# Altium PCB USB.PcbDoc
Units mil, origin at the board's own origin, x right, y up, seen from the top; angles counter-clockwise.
Board outline 5000 x 4000 mil, 2 copper layers (Top Layer, Bottom Layer); 19 components, 24 nets, 79 pads, 4 vias.
Unrouted connection lines stored in the file: 1.
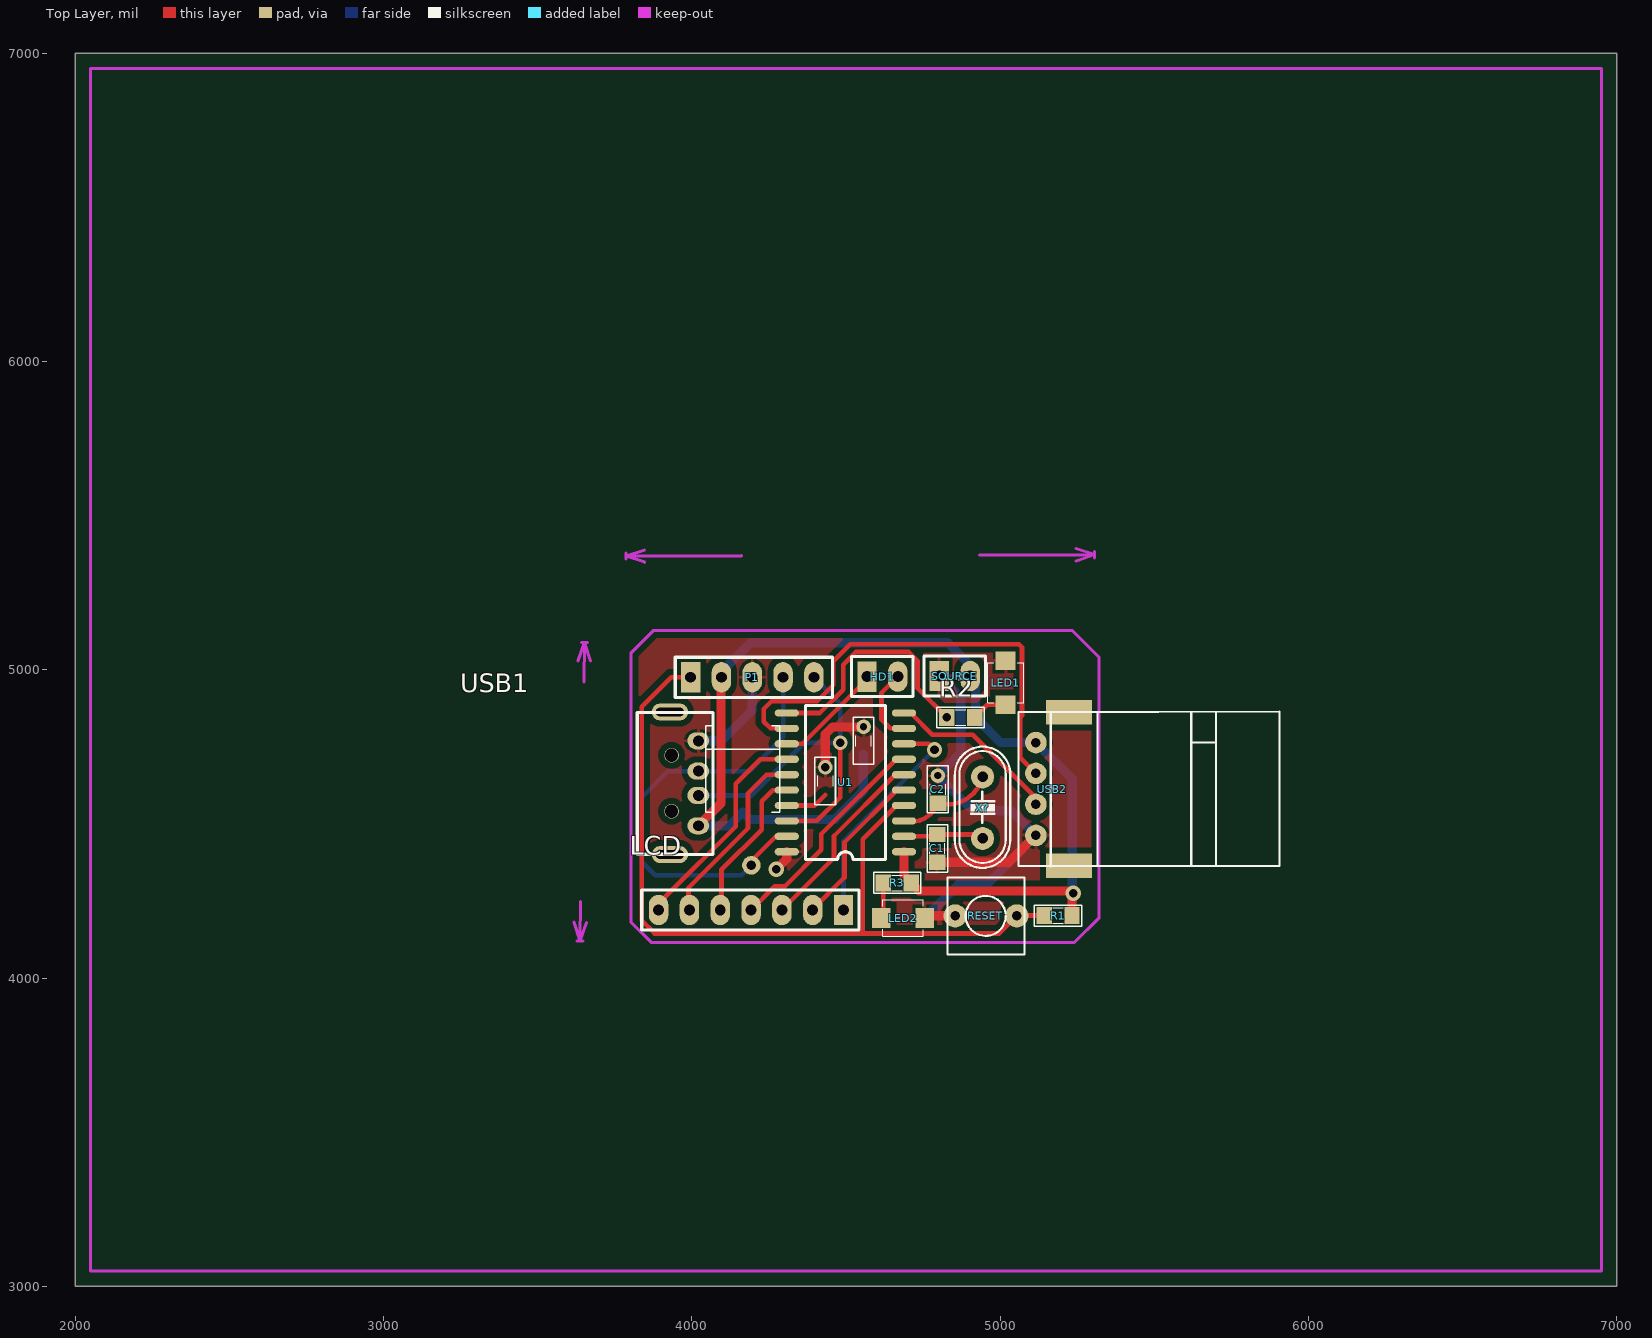
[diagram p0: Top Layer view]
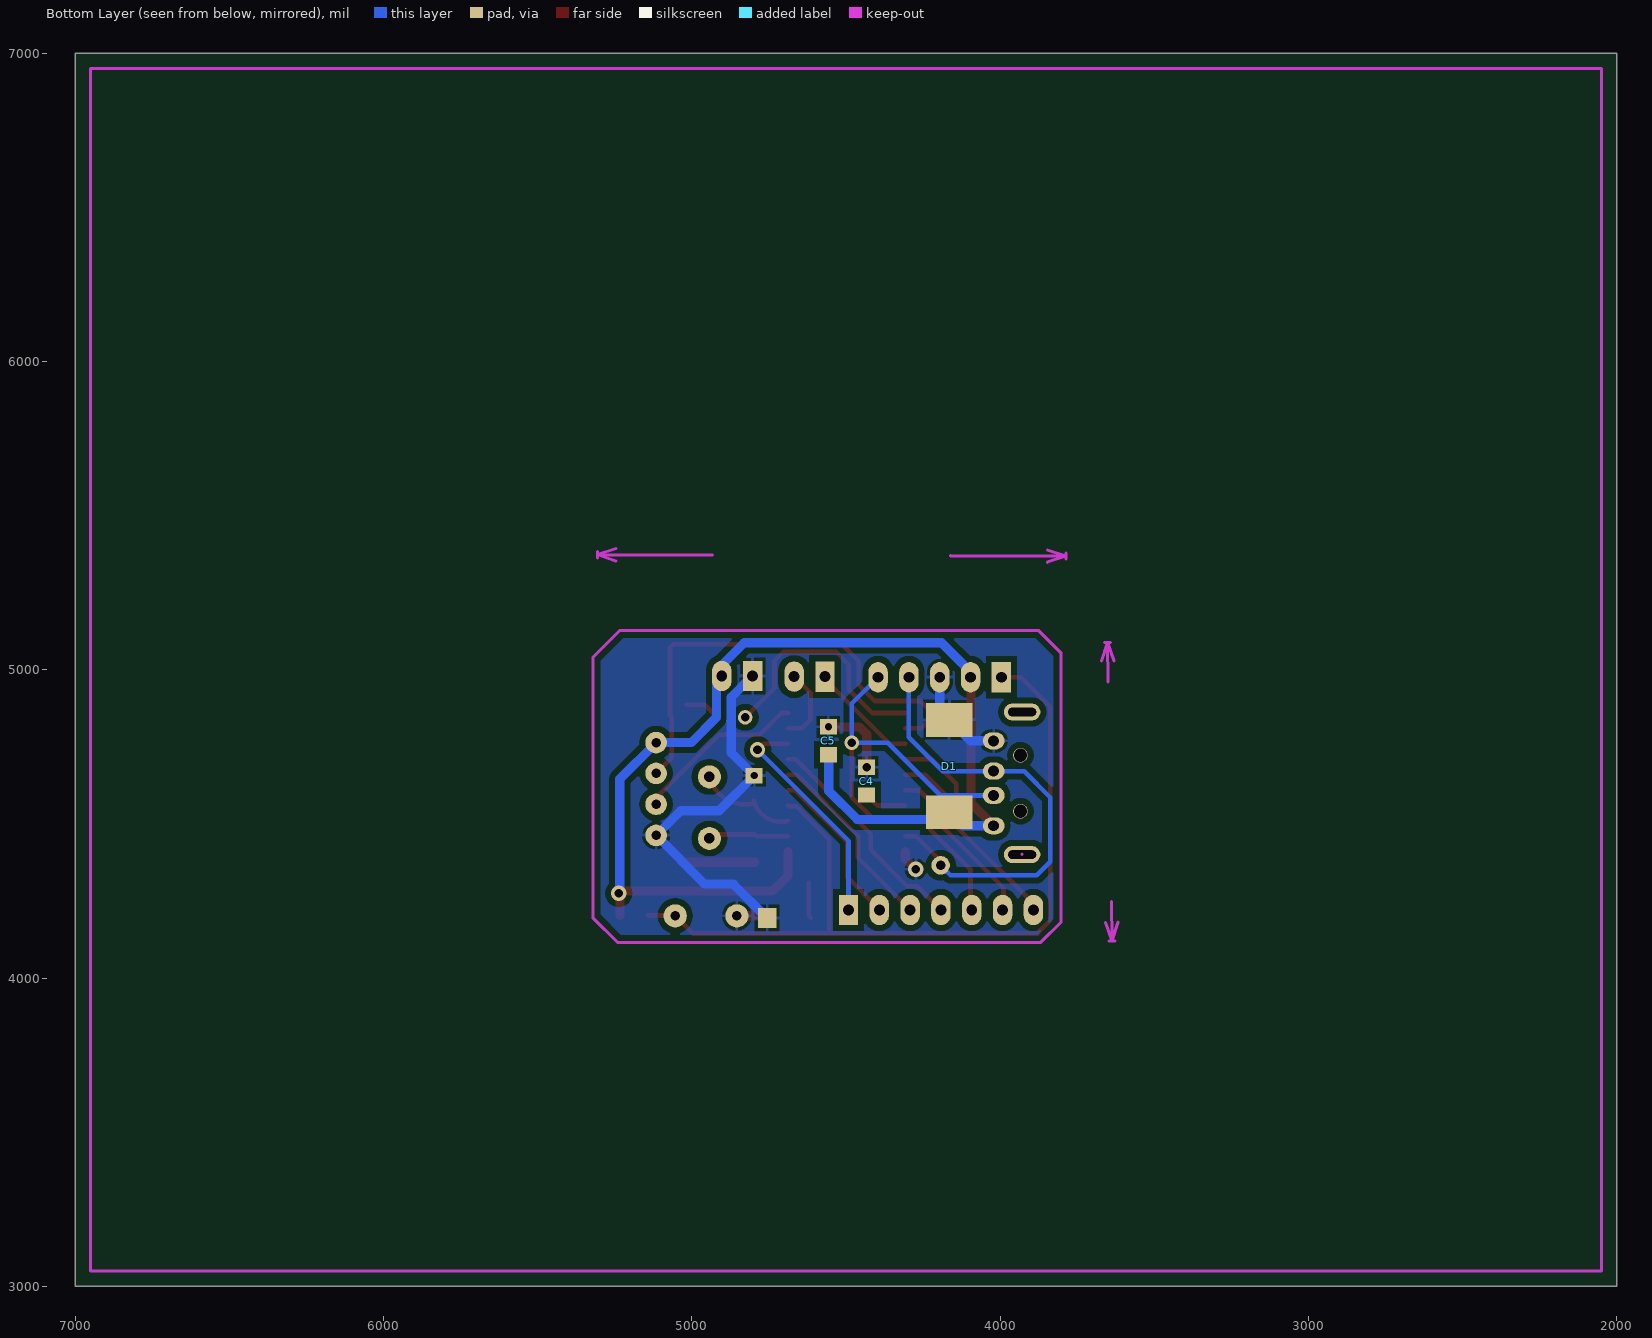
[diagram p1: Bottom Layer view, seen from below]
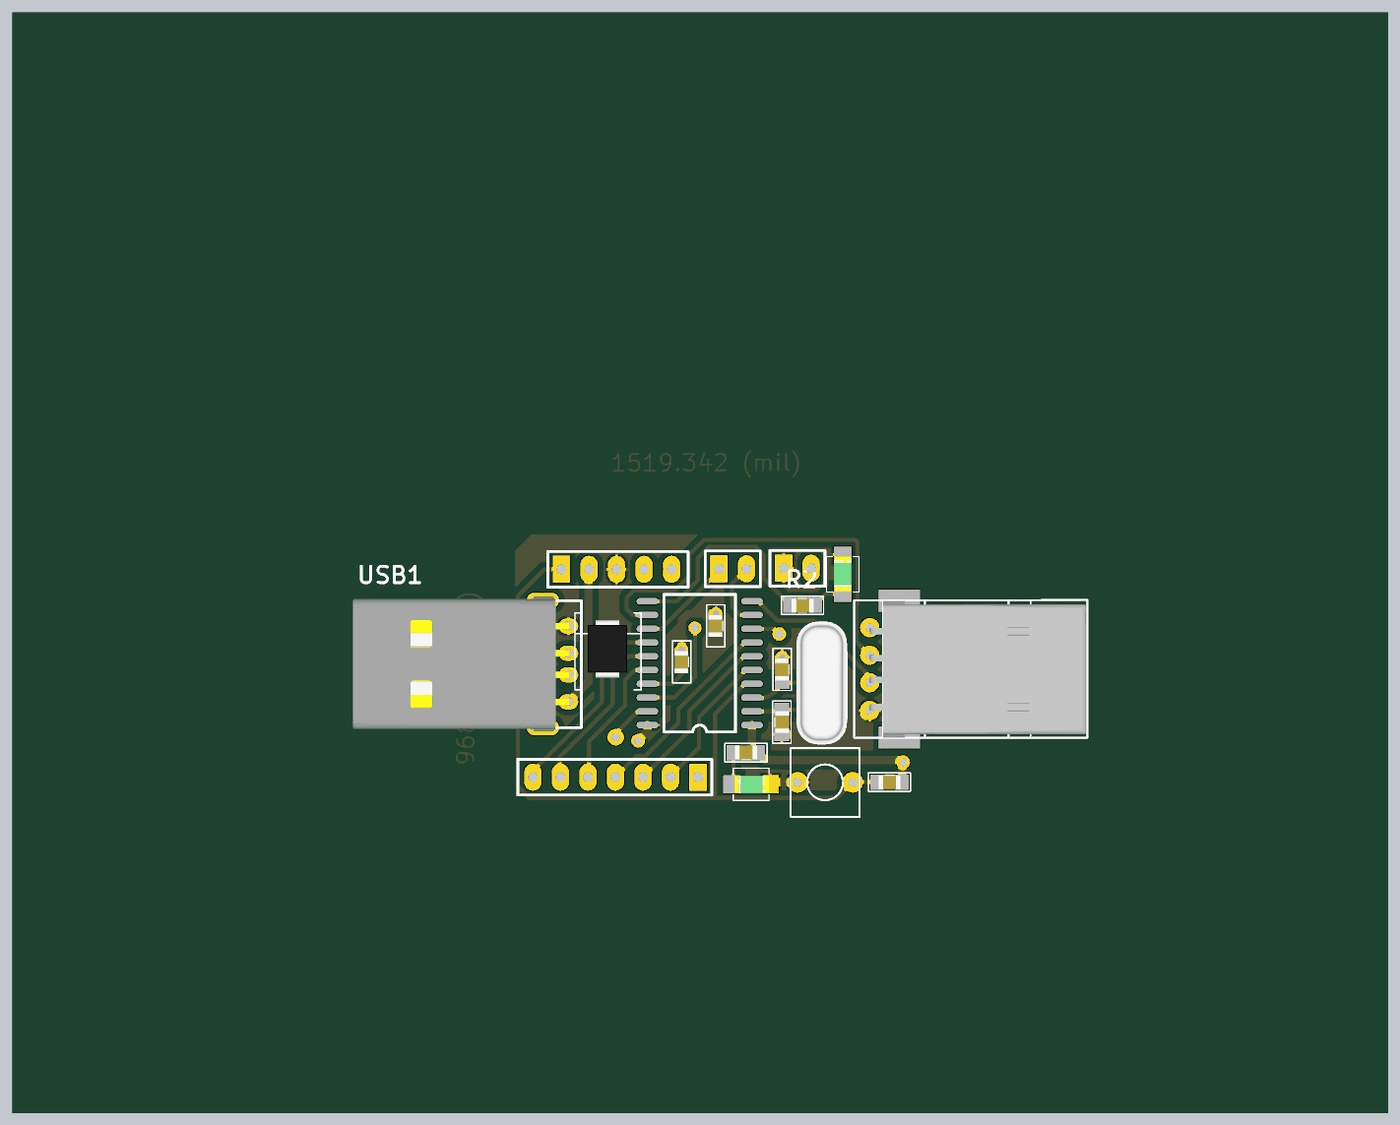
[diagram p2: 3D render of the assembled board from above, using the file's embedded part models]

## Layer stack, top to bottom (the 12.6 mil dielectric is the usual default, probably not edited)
Top Layer: signal copper 1.4
Dielectric: core 12.6, FR-4, Dk 4.8
Bottom Layer: signal copper 1.4

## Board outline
2000,3000 7000,3000 7000,7000 2000,7000

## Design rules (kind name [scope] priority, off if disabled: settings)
Clearance Clearance_2 [InNet('GND') vs InNet('GND')] p1: gap=20
Clearance Clearance_1 [All] p2: gap=20
Clearance [InNet('VCC') vs InNet('VCC')] p3: gap=40
PolygonConnect [All] p1: connectstyle=Relief reliefconductorwidth=10 reliefentries=4 polygonreliefangle="90 Angle" airgapwidth=10
RoutingVias [All] p1: holewidth=25 width=40 viastyle="Through Hole" minholewidth=28 minwidth=50 maxholewidth=28 maxwidth=50
SolderMaskExpansion [All] p1: expansion=4
Width GND [InNet('GND')] p1: maxlimit=30 minlimit=30 preferedwidth=30
Width VCC [InNet('VCC')] p2: maxlimit=30 minlimit=30 preferedwidth=30
Width [All] p3: maxlimit=15 minlimit=15 preferedwidth=15
28 further rules are at their usual default settings.

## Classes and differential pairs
component class USB: C1 C2 C4 C5 D1 HD1 LED1 LED2 P1 R1 R2 R3 RESET SOURCE U1 USB1 USB2 X?

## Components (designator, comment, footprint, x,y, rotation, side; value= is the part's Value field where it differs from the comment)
C1 "33pF" SM-0805#1 4796,4421 r90 top
C2 "33pF" SM-0805#2 4798,4612 r270 top
C4 "103" SM-0805#3 4433,4639 r270 top
C5 "103" SM-0805#3 4557,4770 r270 top
D1 "1N4007" SM-DIODE 4165,4688 r270 top
HD1 "Header 2" HEADER1x2 4568,4978 r0 top
LCD "Header 7H" HEADER1x7 4492,4221 r180 top
LED1 "LED" SM-LED-Red#1 5018,4887 r90 top
LED2 "LED" SM-LED-Red#2 4614,4195 r0 top
P1 "MACH NAP" HEADER1x5 3996,4976 r0 top
R1 "10K" SM-0805#1 5188,4203 r0 top
R2 "1k" SM-0805#1 4872,4846 r0 top
R3 "1k" SM-0805#1 4666,4309 r180 top
RESET "SW" SW2 4854,4202 r0 top
SOURCE "Header 2" HEADER1x2 4803,4980 r0 top
U1 "PIC18F14K50-I/P" SOP-20 4688,4410 r180 top
USB1 "USB-S" USB-A-RA 4018,4632 r270 top
USB2 "USB-S" USB-A 5116,4764 r270 top
X? "4Mhz" XT2 4943,4553 r270 top

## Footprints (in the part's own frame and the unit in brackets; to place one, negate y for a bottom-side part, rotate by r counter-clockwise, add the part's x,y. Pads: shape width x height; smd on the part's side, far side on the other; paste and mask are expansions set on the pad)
HEADER1x2 [mm]
  rect 1.6x2.5 hole 0.9: 1(0,0)
  oval 1.6x2.5 hole 0.9: 2(2.54,0)
  silkscreen extent -1.27,-1.65 3.81,1.65
HEADER1x5 [mm]
  rect 1.6x2.5 hole 0.9: 1(0,0)
  oval 1.6x2.5 hole 0.9: 2(2.54,0) 3(5.08,0) 4(7.62,0) 5(10.16,0)
  silkscreen extent -1.27,-1.65 11.68,1.65
HEADER1x7 [mm]
  rect 1.6x2.5 hole 0.9: 1(0,0)
  oval 1.6x2.5 hole 0.9: 2(2.54,0) 3(5.08,0) 4(7.62,0) 5(10.16,0) 6(12.7,0) 7(15.24,0)
  silkscreen extent -1.27,-1.65 16.63,1.65
SM-0805#1 [mil] "Compoment SMD 80x50mil"
  rect 50x55 smd: 1(-45,0) 2(45,0)
  silkscreen extent -77,-34 76,33, body extent -40,-27 40,23, height 24
SM-0805#2 [mil] "Compoment SMD 80x50mil"
  rect 50x55 smd far side: 1(-45,0)
  rect 50x55 smd: 2(45,0)
  silkscreen extent -77,-34 76,33, body extent -40,-27 40,23, height 24
SM-0805#3 [mil] "Compoment SMD 80x50mil"
  rect 50x55 smd far side: 1(-45,0) 2(45,0)
  silkscreen extent -77,-34 76,33, body extent -40,-27 40,23, height 24
SM-DIODE [mil] "Magnetic-Core Inductor with Winding Polarity Marking; 2 Leads"
  rect 110x150 smd far side: 1(-150,0) 2(150,0)
  silkscreen extent -130,-120 150,120, body extent -103,-73 105,69, height 96
SM-LED-Red#1 [mil]
  rect 60x65 smd: 1(0,0) 2(142,0)
  silkscreen extent 6,-59 136,59, body extent 10,-32 136,31, height 44
SM-LED-Red#2 [mil]
  rect 60x65 smd: 1(0,0)
  rect 60x65 all layers, no hole: 2(142,0)
  silkscreen extent 6,-59 136,59, body extent 10,-32 136,31, height 44
SOP-20 [mm]
  oval 2x0.6 smd: 1(0,0) 2(0,-1.27) 3(0,-2.54) 4(0,-3.81) 5(0,-5.08) 6(0,-6.35) 7(0,-7.62) 8(0,-8.89) 9(0,-10.16) 10(0,-11.43) 11(9.652,-11.43) 12(9.652,-10.16) 13(9.652,-8.89) 14(9.652,-7.62) 15(9.652,-6.35) 16(9.652,-5.08) 17(9.652,-3.81) 18(9.652,-2.54) 19(9.652,-1.27) 20(9.652,0)
  silkscreen extent 1.52,-12.06 8.13,0.64
SW2 [mil] "SW button 2pin, 250x 250 mil"
  round 75 hole 31: 1(0,0) 2(200,0)
  silkscreen extent -25,-125 225,125
USB-A [mil]
  round 70 hole 31: 1(0,0) 2(100,0) 3(200,0) 4(301,0)
  rect 80x150 smd: 5(-98,107) 6(399,107)
  silkscreen extent -101,-57 401,790, body extent -97,0 399,784, height 177
USB-A-RA [mm] "USB Type A"
  oval 1.4x1.8 hole 0.9: 1(3.5,0.08) 2(1,0.08) 3(-1,0.08) 4(-3.5,0.08)
  oval 1.4x3 hole 0.7 slot 2.3 at 90 deg: HOLE(-5.875,-2.27) HOLE(5.875,-2.27)
  round 1.2 hole 1.1: HOLE(-2.3,-2.13) HOLE(2.3,-2.13)
  Keep-Out Layer lines w0.254: 5.875,-2.27 5.842,-2.27
  silkscreen extent -5.84,-4.95 5.87,1.27, body extent -6.25,-19.8 6.25,0.23, height 2.18
XT2 [mil] "Footpin for Crystal 2 pin"
  round 75 hole 34: 1(-100,0) 2(100,0)
  silkscreen extent -198,-90 195,90, body extent -233,-93 213,90, height 138

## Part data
C1 C2 C4 C5: library part CM, "Cap SMD"
D1: library part D1A, "Diode 1A"
HD1 SOURCE: library part Hed2, "Header 2 (Green)"
LCD: "Header, 7-Pin, Right Angle"
LED1 LED2: "LED Single colour Green and Red"
P1: library part "Header 5H", "Header, 5-Pin, Right Angle"
R1 R2 R3: library part R, "Resistor 1/4W"
RESET: library part SW2, "Switch button 2 pin"
U1: "USB Flash Microcontroller with nanoWatt XLP Technology, 20-pin PDIP, Industrial Temperature"
USB1 USB2: library part USB_S, "USB connector"
X?: library part XT2, "Crystal For all Crystal 2pin."

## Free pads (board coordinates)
  round 47.24 hole 23.62: 1(4798,4657) 6(4557,4815)
  round 47.24 hole 27.56: 2(4433,4684) 4(4827,4846)
  round 60 hole 30: 3(4193,4366)

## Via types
v1: diameter 50, hole 28, Top Layer to Bottom Layer, 2 vias
v2: diameter 47.24, hole 27.56, Top Layer to Bottom Layer, 1 vias
v3: diameter 50, hole 27.56, Top Layer to Bottom Layer, 1 vias

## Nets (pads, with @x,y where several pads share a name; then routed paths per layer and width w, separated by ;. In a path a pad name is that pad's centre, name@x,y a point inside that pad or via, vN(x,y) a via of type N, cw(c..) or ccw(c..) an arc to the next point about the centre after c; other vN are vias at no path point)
D4: LCD.4 U1.7 | length 728.7
  Top Layer w15: LCD.4 4269,4298 4302,4298 4420,4416 4420,4467.47 4662.53,4710 U1.7
D5: LCD.3 U1.6 | length 619.4
  Top Layer w15: LCD.3 4461,4390 4461,4461 4660,4660 U1.6
D6: LCD.2 U1.5 | length 525.1
  Top Layer w15: LCD.2 4392,4223.63 4495,4326.63 4495,4440 4665,4610 U1.5
D7: LCD.1 U1.8 | length 749.1
  Top Layer w15: U1.8 4768,4760 v1(4787,4741)
  Bottom Layer w15: LCD.1 4492,4446 v1(4787,4741)
D+: 
D+/PGD: P1.4 pad.3 U1.19 USB1.3 | length 1492.4
  Top Layer w15: pad.3 4193,4380 4273,4460 U1.19
  Bottom Layer w15: pad.3 4161,4334 3881,4334 3837,4378 3837,4586 3922.37,4671.37 USB1.3 4186.37,4671.37 4296,4781 P1.4
D-: 
D-/PGC: P1.5 U1.18 USB1.2 | length 1185.1
  Top Layer w15: U1.18 4405,4510 4481,4586 v2(4481,4763) ; P1.5@4396,4951 P1.5
  Bottom Layer w15: USB1.2 4193.63,4592.63 4364,4763 v2(4481,4763) 4481,4891 P1.5
EN: LCD.7 U1.14 | length 659.6
  Top Layer w15: 3914,4264 4142,4492 4142,4630 4222,4710 U1.14
GND: C1.1 C2.1 C4.1 C5.1 D1.1 LED1.2 LED2.2 P1.3 pad.1 pad.2 pad.6 RESET.1 SOURCE.1 U1.20 USB1.4 USB2.4 | length 2396.4
  Top Layer w30: v1(4274,4353) 4308,4387 U1.20 ; pad.2@4438.38,4689.38 pad.2 4433,4790.87 4457.13,4815 pad.6 ; LED2.2 4763,4202 RESET.1 ; C1.1 5029,4376 USB2.4 ; SOURCE.1 SOURCE.1@4803,5007
  Bottom Layer w30: USB1.4 4096.8,4769.8 D1.1 4196,4869 P1.3 P1.3@4183,4963 ; LED2.2 4866,4305 4958,4305 USB2.4 5036,4543 4912,4543 pad.1 4872,4731 4872,4911 SOURCE.1
LED: pad.4 R2.1 U1.11 | length 787.8
  Top Layer w15: U1.11 4415,4860 4491,4936 4491,5017 4532,5058 4703,5058 4732,5029 4732,4941 R2.1
MCLR: P1.1 R1.1 RESET.2 U1.4 | length 2721.7
  Top Layer w15: P1.1 3933,4976 3837,4880 3837,4187 3879,4145 4997,4145 RESET.2 5055,4203 R1.1 ; 4556,4148.5 4554,4150.5 4554,4451 4661,4558 4686,4558 U1.4
NetC4_2: C4.2 U1.17 | length 139.1
  Top Layer w15: U1.17 4399,4560 4433,4594
NetLED1_1: LED1.1 R2.2 | length 118
  Top Layer w15: R2.2 4958,4887 LED1.1
NetLED2_1: LED2.1 R3.2 | length 116.9
  Top Layer w15: LED2.1 4621,4202 R3.2
OSC1: C1.2 U1.2 X?.2 | length 254.4
  Top Layer w15: U1.2 C1.2@4790,4460 ; C1.2 4930,4466 X?.2
OSC2: C2.2 U1.3 X?.1 | length 330.1
  Top Layer w15: U1.3 ccw(c4711,4598) C2.2@4799,4575 ; C2.2 ccw(c4827.5,4682.5) X?.1
RB4: HD1.1 U1.13 | length 355.6
  Top Layer w15: U1.13 4359,4760 4568,4969 HD1.1
RC7: HD1.2 U1.9 | length 246
  Top Layer w15: HD1.2 4615,4925 4615,4839 4644,4810 U1.9
RS: LCD.5 U1.16 | length 460.2
  Top Layer w15: LCD.5@4096,4264 4096,4351 4227,4482 4227,4574 4263,4610 U1.16
RW: LCD.6 U1.15 | length 566.8
  Top Layer w15: LCD.6@3989,4264 3989,4293 4182,4486 4182,4600 4242,4660 U1.15
RX: U1.12 USB2.2 | length 1531.5
  Top Layer w15: U1.12 4255,4810 4233,4832 4233,4873 4259,4899 4407,4899 4459,4951 4459,5028 4514,5083 5061,5083 5071,5073 5071,4851.5 5065.5,4846 5065.5,4714.5 USB2.2
TX: U1.10 USB2.3 | length 562.9
  Top Layer w15: U1.10 4710,4860 4780,4790 4911,4790 5116,4585 USB2.3
VCC: C5.2 D1.2 P1.2 R1.2 R3.1 SOURCE.2 U1.1 USB1.1 USB2.1 | length 3790.3
  Top Layer w30: USB1.1 4094.5,4567.56 4094.5,4974.5 P1.2 ; U1.1 4688,4332 R3.1 4737,4283 5229,4283 v3(5237,4275) ; R1.2 v3@5233,4271
  Bottom Layer w30: USB1.1 4121.2,4494.2 D1.2 4188,4515 4464,4515 4556,4607 C5.2@4556,4726 ; P1.2 4096,4994 4190,5088 4830,5088 4903,5015 SOURCE.2 4920,4963 4920,4846 5002,4764 USB2.1 5234,4646 5234,4278 v3(5237,4275)
pads on no net: USB1.HOLE USB2.5 USB2.6

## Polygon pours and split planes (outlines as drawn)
GND on Top Layer "Top Layer-No Net" (solid, remove dead copper, pour order 8): 3912,5138 3927,5123 5238,5123 5238,5112 5319,5031 5321,5029 5321,4196 5241,4116 3868,4116 3802,4182 3802,5054 3876,5128
GND on Bottom Layer "Top Layer-No Net" (solid, remove dead copper, pour order 10): 3876,5128 3881,5123 5238,5123 5321,5040 5321,4196 5316,4196 5249,4129 5236,4116 3868,4116 3802,4182 3802,5054 3876,5128

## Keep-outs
Keep-Out Layer:
  lines w10: 3617.93,4181.3 3637,4121 ; 3627,4121.15 3647,4120.85 ; 3631.07,5029.32 3652,5089 ; 3638.99,4249.15 3637,4121 ; 3642,5089.15 3662,5088.85 ; 3650.01,4960.85 3652,5089 ; 3657.93,4180.68 3637,4121 ; 3671.07,5028.7 3652,5089 ; 3786.97,5379 3787.03,5359 ; 3846.94,5389.18 3787,5369 ; 3847.06,5349.18 3787,5369 ; 4160.79,5370.1 3787,5369 ; 4932.55,5372.36 5306.34,5373.46 ; 5246.28,5393.28 5306.34,5373.46 ; 5246.39,5353.28 5306.34,5373.46 ; 5306.31,5383.46 5306.36,5363.46 ; 2050,3050 6950,3050 6950,6950 2050,6950 2050,3050 ; 3802,4182 3868,4116 5241,4116 5321,4196 5321,5040 5233,5128 3876,5128 3802,5054 3802,4182
  text "1519.342 (mil)" at 4170.89,5334.14 h60 r0.17
  text "968.116 (mil)" at 3675.13,4258.59 h60 r89.11

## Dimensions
2050,3050 to 6950,3050 on Mechanical 1
2050,3050 to 2050,6950 on Mechanical 1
